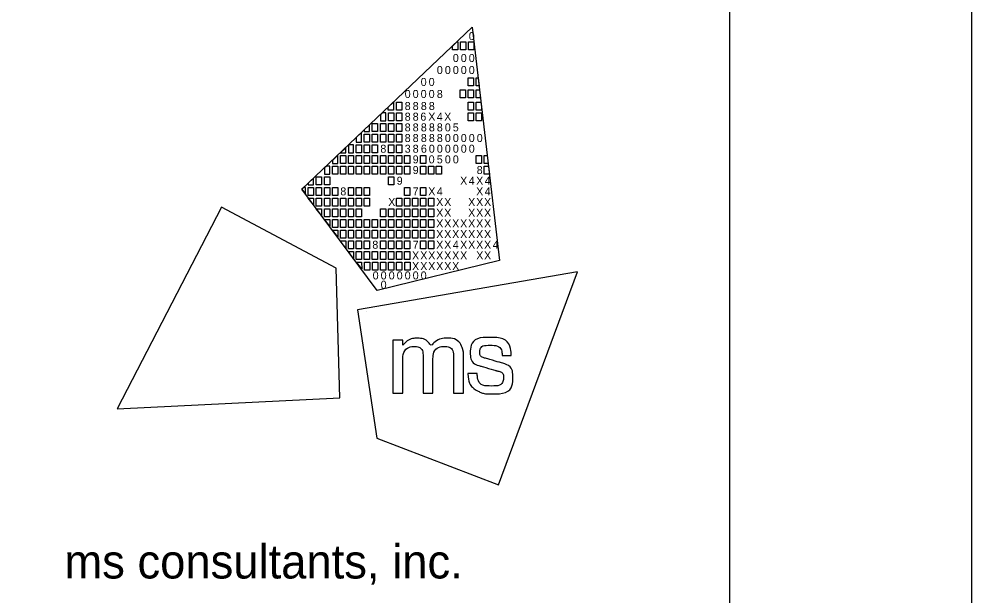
# Model space of a CAD drawing. Extents: x 0 to 34, y 0 to 22.
# Drawn here: x 32.034 to 34, y 3.413 to 4.603 of the extents above; entities that cross this region are included whole.
import ezdxf

# ---------------------------------------------------------------- set-up
doc = ezdxf.new("R2010")
doc.units = 0
for name, color, linetype in [('SH_Border', 7, 'Continuous'), ('SH_Cut_Line', 7, 'Continuous'), ('SH_Data', 7, 'Continuous')]:
    doc.layers.add(name, color=color, linetype=linetype)

msp = doc.modelspace()

# ---------------------------------------------------------------- linework, layer by layer
at = {"layer": 'SH_Border'}
for p, q in [((32.6175, 4.2519), (32.9688, 4.5861)), ((32.9688, 4.5861), (32.9688, 4.5861)), ((32.9688, 4.5861), (33.0253, 4.1052)), ((32.773, 4.043), (32.6175, 4.2519)), ((33.0253, 4.1052), (32.773, 4.043))]:
    msp.add_line(p, q, dxfattribs=at)
for points in [[(1.5, 21.5), (33.5, 21.5), (33.5, 0.5), (1.5, 0.5)], [(32.9279, 4.5472), (32.9369, 4.5558), (32.9389, 4.5558), (32.9389, 4.5393), (32.9279, 4.5393)], [(32.9444, 4.5558), (32.9554, 4.5558), (32.9554, 4.5393), (32.9444, 4.5393)], [(32.9609, 4.5558), (32.9719, 4.5558), (32.9719, 4.5393), (32.9609, 4.5393)], [(32.9606, 4.4815), (32.9716, 4.4815), (32.9716, 4.465), (32.9606, 4.465)], [(32.9771, 4.4815), (32.9811, 4.4815), (32.983, 4.465), (32.9771, 4.465)], [(32.9441, 4.4567), (32.9551, 4.4567), (32.9551, 4.4402), (32.9441, 4.4402)], [(32.9606, 4.4567), (32.9716, 4.4567), (32.9716, 4.4402), (32.9606, 4.4402)], [(32.9771, 4.4567), (32.984, 4.4567), (32.9859, 4.4402), (32.9771, 4.4402)], [(32.7953, 4.4211), (32.8064, 4.4316), (32.8064, 4.4154), (32.7953, 4.4154)], [(32.8123, 4.4319), (32.8233, 4.4319), (32.8233, 4.4154), (32.8123, 4.4154)], [(32.9606, 4.4319), (32.9716, 4.4319), (32.9716, 4.4154), (32.9606, 4.4154)], [(32.9771, 4.4319), (32.9869, 4.4319), (32.9881, 4.4218), (32.9881, 4.4154), (32.9771, 4.4154)], [(32.7958, 4.4099), (32.8068, 4.4099), (32.8068, 4.3934), (32.7958, 4.3934)], [(32.8123, 4.4099), (32.8233, 4.4099), (32.8233, 4.3934), (32.8123, 4.3934)], [(32.9606, 4.4099), (32.9716, 4.4099), (32.9716, 4.3934), (32.9606, 4.3934)], [(32.9771, 4.4099), (32.9881, 4.4099), (32.9881, 4.3934), (32.9771, 4.3934)], [(32.7627, 4.3879), (32.7737, 4.3879), (32.7737, 4.3714), (32.7627, 4.3714)], [(32.7793, 4.3879), (32.7903, 4.3879), (32.7903, 4.3714), (32.7793, 4.3714)], [(32.7958, 4.3879), (32.8068, 4.3879), (32.8068, 4.3714), (32.7958, 4.3714)], [(32.8123, 4.3879), (32.8233, 4.3879), (32.8233, 4.3714), (32.8123, 4.3714)], [(32.7462, 4.3659), (32.7572, 4.3659), (32.7572, 4.3494), (32.7462, 4.3494)], [(32.7627, 4.3659), (32.7737, 4.3659), (32.7737, 4.3494), (32.7627, 4.3494)], [(32.7793, 4.3659), (32.7903, 4.3659), (32.7903, 4.3494), (32.7793, 4.3494)], [(32.7958, 4.3659), (32.8068, 4.3659), (32.8068, 4.3494), (32.7958, 4.3494)], [(32.8123, 4.3659), (32.8233, 4.3659), (32.8233, 4.3494), (32.8123, 4.3494)], [(32.7297, 4.3439), (32.7407, 4.3439), (32.7407, 4.3273), (32.7297, 4.3273)], [(32.7462, 4.3439), (32.7572, 4.3439), (32.7572, 4.3273), (32.7462, 4.3273)], [(32.7627, 4.3439), (32.7737, 4.3439), (32.7737, 4.3273), (32.7627, 4.3273)], [(32.7958, 4.3439), (32.8068, 4.3439), (32.8068, 4.3273), (32.7958, 4.3273)], [(32.8123, 4.3439), (32.8233, 4.3439), (32.8233, 4.3273), (32.8123, 4.3273)], [(32.6967, 4.3218), (32.7077, 4.3218), (32.7077, 4.3053), (32.6967, 4.3053)], [(32.7132, 4.3218), (32.7242, 4.3218), (32.7242, 4.3053), (32.7132, 4.3053)], [(32.7297, 4.3218), (32.7407, 4.3218), (32.7407, 4.3053), (32.7297, 4.3053)], [(32.7462, 4.3218), (32.7572, 4.3218), (32.7572, 4.3053), (32.7462, 4.3053)], [(32.7627, 4.3218), (32.7737, 4.3218), (32.7737, 4.3053), (32.7627, 4.3053)], [(32.7793, 4.3218), (32.7903, 4.3218), (32.7903, 4.3053), (32.7793, 4.3053)], [(32.7958, 4.3218), (32.8068, 4.3218), (32.8068, 4.3053), (32.7958, 4.3053)], [(32.8123, 4.3218), (32.8233, 4.3218), (32.8233, 4.3053), (32.8123, 4.3053)], [(32.8288, 4.3218), (32.8398, 4.3218), (32.8398, 4.3053), (32.8288, 4.3053)], [(32.8618, 4.3218), (32.8728, 4.3218), (32.8728, 4.3053), (32.8618, 4.3053)], [(32.9771, 4.3218), (32.9881, 4.3218), (32.9881, 4.3053), (32.9771, 4.3053)], [(32.9935, 4.3218), (32.9998, 4.3218), (33.0018, 4.3053), (32.9935, 4.3053)], [(32.6802, 4.2998), (32.6912, 4.2998), (32.6912, 4.2833), (32.6802, 4.2833)], [(32.6967, 4.2998), (32.7077, 4.2998), (32.7077, 4.2833), (32.6967, 4.2833)], [(32.7132, 4.2998), (32.7242, 4.2998), (32.7242, 4.2833), (32.7132, 4.2833)], [(32.7297, 4.2998), (32.7407, 4.2998), (32.7407, 4.2833), (32.7297, 4.2833)], [(32.7462, 4.2998), (32.7572, 4.2998), (32.7572, 4.2833), (32.7462, 4.2833)], [(32.7627, 4.2998), (32.7737, 4.2998), (32.7737, 4.2833), (32.7627, 4.2833)], [(32.7793, 4.2998), (32.7903, 4.2998), (32.7903, 4.2833), (32.7793, 4.2833)], [(32.7958, 4.2998), (32.8068, 4.2998), (32.8068, 4.2833), (32.7958, 4.2833)], [(32.8123, 4.2998), (32.8233, 4.2998), (32.8233, 4.2833), (32.8123, 4.2833)], [(32.8288, 4.2998), (32.8398, 4.2998), (32.8398, 4.2833), (32.8288, 4.2833)], [(32.8618, 4.2998), (32.8728, 4.2998), (32.8728, 4.2833), (32.8618, 4.2833)], [(32.8783, 4.2998), (32.8893, 4.2998), (32.8893, 4.2833), (32.8783, 4.2833)], [(32.8947, 4.2998), (32.9057, 4.2998), (32.9057, 4.2833), (32.8947, 4.2833)], [(32.9935, 4.2998), (33.0024, 4.2998), (33.0044, 4.2833), (32.9935, 4.2833)], [(32.6471, 4.2778), (32.6581, 4.2778), (32.6581, 4.2613), (32.6471, 4.2613)], [(32.6637, 4.2778), (32.6747, 4.2778), (32.6747, 4.2613), (32.6637, 4.2613)], [(32.7958, 4.2778), (32.8068, 4.2778), (32.8068, 4.2613), (32.7958, 4.2613)], [(32.6306, 4.2558), (32.6416, 4.2558), (32.6416, 4.2393), (32.6306, 4.2393)], [(32.6471, 4.2558), (32.6581, 4.2558), (32.6581, 4.2393), (32.6471, 4.2393)], [(32.6637, 4.2558), (32.6747, 4.2558), (32.6747, 4.2393), (32.6637, 4.2393)], [(32.6802, 4.2558), (32.6912, 4.2558), (32.6912, 4.2393), (32.6802, 4.2393)], [(32.7132, 4.2558), (32.7242, 4.2558), (32.7242, 4.2393), (32.7132, 4.2393)], [(32.7297, 4.2558), (32.7407, 4.2558), (32.7407, 4.2393), (32.7297, 4.2393)], [(32.7462, 4.2558), (32.7572, 4.2558), (32.7572, 4.2393), (32.7462, 4.2393)], [(32.8288, 4.2558), (32.8398, 4.2558), (32.8398, 4.2393), (32.8288, 4.2393)], [(32.8618, 4.2558), (32.8728, 4.2558), (32.8728, 4.2393), (32.8618, 4.2393)], [(32.6306, 4.2338), (32.6416, 4.2338), (32.6416, 4.22)], [(32.6471, 4.2338), (32.6581, 4.2338), (32.6581, 4.2173), (32.6471, 4.2173)], [(32.6637, 4.2338), (32.6747, 4.2338), (32.6747, 4.2173), (32.6637, 4.2173)], [(32.6802, 4.2338), (32.6912, 4.2338), (32.6912, 4.2173), (32.6802, 4.2173)], [(32.6967, 4.2338), (32.7077, 4.2338), (32.7077, 4.2173), (32.6967, 4.2173)], [(32.7132, 4.2338), (32.7242, 4.2338), (32.7242, 4.2173), (32.7132, 4.2173)], [(32.7297, 4.2338), (32.7407, 4.2338), (32.7407, 4.2173), (32.7297, 4.2173)], [(32.7462, 4.2338), (32.7572, 4.2338), (32.7572, 4.2173), (32.7462, 4.2173)], [(32.8123, 4.2338), (32.8233, 4.2338), (32.8233, 4.2173), (32.8123, 4.2173)], [(32.8288, 4.2338), (32.8398, 4.2338), (32.8398, 4.2173), (32.8288, 4.2173)], [(32.8453, 4.2338), (32.8563, 4.2338), (32.8563, 4.2173), (32.8453, 4.2173)], [(32.8618, 4.2338), (32.8728, 4.2338), (32.8728, 4.2173), (32.8618, 4.2173)], [(32.8783, 4.2338), (32.8893, 4.2338), (32.8893, 4.2173), (32.8783, 4.2173)], [(32.6471, 4.2117), (32.6581, 4.2117), (32.6581, 4.198)], [(32.6637, 4.2117), (32.6747, 4.2117), (32.6747, 4.1952), (32.6637, 4.1952)], [(32.6802, 4.2117), (32.6912, 4.2117), (32.6912, 4.1952), (32.6802, 4.1952)], [(32.6967, 4.2117), (32.7077, 4.2117), (32.7077, 4.1952), (32.6967, 4.1952)], [(32.7132, 4.2117), (32.7242, 4.2117), (32.7242, 4.1952), (32.7132, 4.1952)], [(32.7297, 4.2117), (32.7407, 4.2117), (32.7407, 4.1952), (32.7297, 4.1952)], [(32.7793, 4.2117), (32.7903, 4.2117), (32.7903, 4.1952), (32.7793, 4.1952)], [(32.7958, 4.2117), (32.8068, 4.2117), (32.8068, 4.1952), (32.7958, 4.1952)], [(32.8123, 4.2117), (32.8233, 4.2117), (32.8233, 4.1952), (32.8123, 4.1952)], [(32.8288, 4.2117), (32.8398, 4.2117), (32.8398, 4.1952), (32.8288, 4.1952)], [(32.8453, 4.2117), (32.8563, 4.2117), (32.8563, 4.1952), (32.8453, 4.1952)], [(32.8618, 4.2117), (32.8728, 4.2117), (32.8728, 4.1952), (32.8618, 4.1952)], [(32.8783, 4.2117), (32.8893, 4.2117), (32.8893, 4.1952), (32.8783, 4.1952)], [(32.6637, 4.1897), (32.6747, 4.1897), (32.6747, 4.176)], [(32.6747, 4.1897), (32.6747, 4.1897), (32.6747, 4.1897)], [(32.6802, 4.1897), (32.6912, 4.1897), (32.6912, 4.1732), (32.6802, 4.1732)], [(32.6967, 4.1897), (32.7077, 4.1897), (32.7077, 4.1732), (32.6967, 4.1732)], [(32.7132, 4.1897), (32.7242, 4.1897), (32.7242, 4.1732), (32.7132, 4.1732)], [(32.7297, 4.1897), (32.7407, 4.1897), (32.7407, 4.1732), (32.7297, 4.1732)], [(32.7462, 4.1897), (32.7572, 4.1897), (32.7572, 4.1732), (32.7462, 4.1732)], [(32.7627, 4.1897), (32.7737, 4.1897), (32.7737, 4.1732), (32.7627, 4.1732)], [(32.7793, 4.1897), (32.7903, 4.1897), (32.7903, 4.1732), (32.7793, 4.1732)], [(32.7958, 4.1897), (32.8068, 4.1897), (32.8068, 4.1732), (32.7958, 4.1732)], [(32.8123, 4.1897), (32.8233, 4.1897), (32.8233, 4.1732), (32.8123, 4.1732)], [(32.8288, 4.1897), (32.8398, 4.1897), (32.8398, 4.1732), (32.8288, 4.1732)], [(32.8453, 4.1897), (32.8563, 4.1897), (32.8563, 4.1732), (32.8453, 4.1732)], [(32.8618, 4.1897), (32.8728, 4.1897), (32.8728, 4.1732), (32.8618, 4.1732)], [(32.8783, 4.1897), (32.8893, 4.1897), (32.8893, 4.1732), (32.8783, 4.1732)], [(32.6802, 4.1677), (32.6912, 4.1677), (32.6912, 4.154)], [(32.6967, 4.1677), (32.7077, 4.1677), (32.7077, 4.1512), (32.6967, 4.1512)], [(32.7132, 4.1677), (32.7242, 4.1677), (32.7242, 4.1512), (32.7132, 4.1512)], [(32.7297, 4.1677), (32.7407, 4.1677), (32.7407, 4.1512), (32.7297, 4.1512)], [(32.7462, 4.1677), (32.7572, 4.1677), (32.7572, 4.1512), (32.7462, 4.1512)], [(32.7627, 4.1677), (32.7737, 4.1677), (32.7737, 4.1512), (32.7627, 4.1512)], [(32.7793, 4.1677), (32.7903, 4.1677), (32.7903, 4.1512), (32.7793, 4.1512)], [(32.7958, 4.1677), (32.8068, 4.1677), (32.8068, 4.1512), (32.7958, 4.1512)], [(32.8123, 4.1677), (32.8233, 4.1677), (32.8233, 4.1512), (32.8123, 4.1512)], [(32.8288, 4.1677), (32.8398, 4.1677), (32.8398, 4.1512), (32.8288, 4.1512)], [(32.8453, 4.1677), (32.8563, 4.1677), (32.8563, 4.1512), (32.8453, 4.1512)], [(32.8618, 4.1677), (32.8728, 4.1677), (32.8728, 4.1512), (32.8618, 4.1512)], [(32.8783, 4.1677), (32.8893, 4.1677), (32.8893, 4.1512), (32.8783, 4.1512)], [(32.7077, 4.1305), (32.6965, 4.1457), (32.7077, 4.1457)], [(32.7132, 4.1457), (32.7242, 4.1457), (32.7242, 4.1292), (32.7132, 4.1292)], [(32.7297, 4.1457), (32.7407, 4.1457), (32.7407, 4.1292), (32.7297, 4.1292)], [(32.7462, 4.1457), (32.7572, 4.1457), (32.7572, 4.1292), (32.7462, 4.1292)], [(32.7793, 4.1457), (32.7903, 4.1457), (32.7903, 4.1292), (32.7793, 4.1292)], [(32.7958, 4.1457), (32.8068, 4.1457), (32.8068, 4.1292), (32.7958, 4.1292)], [(32.8123, 4.1457), (32.8233, 4.1457), (32.8233, 4.1292), (32.8123, 4.1292)], [(32.8288, 4.1457), (32.8398, 4.1457), (32.8398, 4.1292), (32.8288, 4.1292)], [(32.8618, 4.1457), (32.8728, 4.1457), (32.8728, 4.1292), (32.8618, 4.1292)], [(32.8783, 4.1457), (32.8893, 4.1457), (32.8893, 4.1292), (32.8783, 4.1292)], [(32.724, 4.1082), (32.7132, 4.1237), (32.7242, 4.1237)], [(32.7297, 4.1237), (32.7407, 4.1237), (32.7407, 4.1072), (32.7297, 4.1072)], [(32.7462, 4.1237), (32.7572, 4.1237), (32.7572, 4.1072), (32.7462, 4.1072)], [(32.7627, 4.1237), (32.7737, 4.1237), (32.7737, 4.1072), (32.7627, 4.1072)], [(32.7793, 4.1237), (32.7903, 4.1237), (32.7903, 4.1072), (32.7793, 4.1072)], [(32.7958, 4.1237), (32.8068, 4.1237), (32.8068, 4.1072), (32.7958, 4.1072)], [(32.8123, 4.1237), (32.8233, 4.1237), (32.8233, 4.1072), (32.8123, 4.1072)], [(32.8288, 4.1237), (32.8398, 4.1237), (32.8398, 4.1072), (32.8288, 4.1072)], [(32.7302, 4.1017), (32.7407, 4.1017), (32.7408, 4.0875)], [(32.7463, 4.1017), (32.7573, 4.1017), (32.7573, 4.0852), (32.7463, 4.0852)], [(32.763, 4.1017), (32.774, 4.1017), (32.774, 4.0852), (32.763, 4.0852)], [(32.7794, 4.1017), (32.7904, 4.1017), (32.7904, 4.0852), (32.7794, 4.0852)], [(32.796, 4.1017), (32.807, 4.1017), (32.807, 4.0852), (32.796, 4.0852)], [(32.8129, 4.1017), (32.8239, 4.1017), (32.8239, 4.0851), (32.8129, 4.0851)], [(32.8296, 4.1017), (32.8406, 4.1017), (32.8406, 4.0851), (32.8296, 4.0851)]]:
    msp.add_lwpolyline(points, close=True, dxfattribs=at)
for points in [[(32.7903, 4.4099), (32.7836, 4.4099), (32.7793, 4.4058), (32.7793, 4.3934), (32.7903, 4.3934), (32.7903, 4.4099)], [(32.7572, 4.3849), (32.7462, 4.3744), (32.7462, 4.3714), (32.7572, 4.3714), (32.7572, 4.3849)], [(32.7407, 4.3691), (32.7297, 4.3587), (32.7297, 4.3494), (32.7407, 4.3494), (32.7407, 4.3691)], [(32.7077, 4.3377), (32.6968, 4.3273), (32.7077, 4.3273), (32.7077, 4.3377)], [(32.7242, 4.3439), (32.7141, 4.3439), (32.7132, 4.343), (32.7132, 4.3273), (32.7242, 4.3273), (32.7242, 4.3439)], [(32.6912, 4.322), (32.6802, 4.3115), (32.6802, 4.3053), (32.6912, 4.3053), (32.6912, 4.322)], [(32.6747, 4.2998), (32.6679, 4.2998), (32.6637, 4.2958), (32.6637, 4.2833), (32.6747, 4.2833), (32.6747, 4.2998)], [(32.6416, 4.2749), (32.6306, 4.2644), (32.6306, 4.2613), (32.6416, 4.2613), (32.6416, 4.2749)], [(32.6251, 4.2558), (32.6216, 4.2558), (32.6175, 4.2519), (32.6251, 4.2417), (32.6251, 4.2558)], [(32.4512, 4.2149), (32.2359, 3.7988), (32.6956, 3.8215), (32.6884, 4.0892), (32.4512, 4.2149)], [(33.0229, 3.6422), (33.1859, 4.0814), (32.7324, 4.0029), (32.7722, 3.7381), (33.0229, 3.6422)]]:
    msp.add_lwpolyline(points, dxfattribs=at)
for points in [[(32.8048, 3.8315), (32.8048, 3.8315), (32.8048, 3.9409), (32.8048, 3.9409), (32.8048, 3.9409), (32.8255, 3.9409), (32.8255, 3.9409), (32.8255, 3.9409), (32.8255, 3.9297), (32.8255, 3.9297), (32.8346, 3.9399), (32.8457, 3.9445), (32.8555, 3.9445), (32.8688, 3.9445), (32.8791, 3.9372), (32.8837, 3.9266), (32.8915, 3.9381), (32.905, 3.9446), (32.9166, 3.9446), (32.9325, 3.9446), (32.9451, 3.935), (32.9494, 3.9213), (32.9494, 3.9212), (32.9494, 3.9212), (32.9494, 3.9212), (32.9501, 3.919), (32.9506, 3.9172), (32.9506, 3.9071), (32.9506, 3.9071), (32.9506, 3.8314), (32.9506, 3.8314), (32.9506, 3.8314), (32.9303, 3.8314), (32.9303, 3.8314), (32.9303, 3.8314), (32.9303, 3.9048), (32.9303, 3.9048), (32.9303, 3.9201), (32.9219, 3.9274), (32.911, 3.9274), (32.8995, 3.9274), (32.8879, 3.9171), (32.8879, 3.9001), (32.8879, 3.9001), (32.8879, 3.8315), (32.8879, 3.8315), (32.8879, 3.8315), (32.8674, 3.8315), (32.8674, 3.8315), (32.8674, 3.8315), (32.8674, 3.9059), (32.8674, 3.9059), (32.8674, 3.9203), (32.8588, 3.9274), (32.8496, 3.9274), (32.8384, 3.9274), (32.8254, 3.917), (32.8254, 3.8962), (32.8254, 3.8962), (32.8254, 3.8315), (32.8254, 3.8315), (32.8254, 3.8315), (32.8048, 3.8315), (32.8048, 3.8315)], [(32.9595, 3.8709), (32.9595, 3.8709), (32.9595, 3.8717), (32.9595, 3.8717), (32.9595, 3.8717), (32.9603, 3.8717), (32.9603, 3.8717), (32.9603, 3.8717), (32.9783, 3.8717), (32.9783, 3.8717), (32.9783, 3.8717), (32.9789, 3.8717), (32.9789, 3.8717), (32.9789, 3.8717), (32.979, 3.871), (32.979, 3.871), (32.9803, 3.8554), (32.9887, 3.846), (33.009, 3.846), (33.0273, 3.846), (33.0333, 3.8554), (33.0333, 3.8631), (33.0333, 3.8732), (33.0256, 3.8758), (33.0175, 3.878), (33.0175, 3.878), (32.987, 3.8867), (32.987, 3.8867), (32.972, 3.8909), (32.9648, 3.9019), (32.9648, 3.9142), (32.9648, 3.9303), (32.9768, 3.9462), (33.0052, 3.9462), (33.0348, 3.9462), (33.0489, 3.9285), (33.0489, 3.9095), (33.0489, 3.9095), (33.0489, 3.9087), (33.0489, 3.9087), (33.0489, 3.9087), (33.0482, 3.9087), (33.0482, 3.9087), (33.0482, 3.9087), (33.0312, 3.9087), (33.0312, 3.9087), (33.0312, 3.9087), (33.0305, 3.9087), (33.0305, 3.9087), (33.0305, 3.9087), (33.0305, 3.9094), (33.0305, 3.9094), (33.0301, 3.9208), (33.0226, 3.93), (33.0056, 3.93), (32.9891, 3.93), (32.9843, 3.9218), (32.9843, 3.9157), (32.9843, 3.9108), (32.9869, 3.9059), (32.9959, 3.9033), (32.9959, 3.9033), (33.0255, 3.8948), (33.0255, 3.8948), (33.0462, 3.8889), (33.0527, 3.8777), (33.0527, 3.8639), (33.0527, 3.8462), (33.041, 3.8298), (33.0087, 3.8298), (32.9952, 3.8298), (32.9877, 3.8321), (32.9823, 3.8348), (32.969, 3.8414), (32.9609, 3.8536), (32.9595, 3.8709)]]:
    msp.add_open_spline(points, degree=3, dxfattribs=at)
at = {"layer": 'SH_Cut_Line'}
msp.add_lwpolyline([(0, 0), (34, 0), (34, 22), (0, 22)], close=True, dxfattribs=at)
at = {"layer": 'SH_Data'}
msp.add_line((32.75, 4), (32.75, 4), dxfattribs=at)

# ---------------------------------------------------------------- texts
at = {"layer": 'SH_Border'}
for s, height, p in [('0', 0.0165, (32.9617, 4.5597)), ('0', 0.0165, (32.9288, 4.5145)), ('0', 0.0165, (32.9452, 4.5145)), ('0', 0.0165, (32.9617, 4.5145)), ('0', 0.0165, (32.8958, 4.4897)), ('0', 0.0165, (32.9123, 4.4897)), ('0', 0.0165, (32.9288, 4.4897)), ('0', 0.0165, (32.9452, 4.4897)), ('0', 0.0165, (32.9617, 4.4897)), ('0', 0.0165, (32.8625, 4.465)), ('0', 0.0165, (32.879, 4.465)), ('0', 0.0165, (32.8295, 4.4402)), ('0', 0.0165, (32.846, 4.4402)), ('0', 0.0165, (32.8625, 4.4402)), ('0', 0.0165, (32.879, 4.4402)), ('8', 0.0165, (32.8958, 4.4402)), ('8', 0.0165, (32.8295, 4.4154)), ('8', 0.0165, (32.846, 4.4154)), ('8', 0.0165, (32.8628, 4.4154)), ('8', 0.0165, (32.8793, 4.4154)), ('8', 0.0165, (32.8295, 4.3934)), ('8', 0.0165, (32.846, 4.3934)), ('6', 0.0165, (32.8618, 4.3934)), ('X', 0.0165, (32.8781, 4.3934)), ('4', 0.0165, (32.8958, 4.3934)), ('X', 0.0165, (32.911, 4.3934)), ('8', 0.0165, (32.8295, 4.3713)), ('8', 0.0165, (32.846, 4.3713)), ('8', 0.0165, (32.8628, 4.3713)), ('8', 0.0165, (32.8794, 4.3713)), ('8', 0.0165, (32.8958, 4.3713)), ('0', 0.0165, (32.9123, 4.3713)), ('5', 0.0165, (32.9287, 4.3713)), ('8', 0.0165, (32.8295, 4.3494)), ('8', 0.0165, (32.846, 4.3494)), ('8', 0.0165, (32.8628, 4.3494)), ('8', 0.0165, (32.8794, 4.3494)), ('8', 0.0165, (32.8958, 4.3494)), ('0', 0.0165, (32.9123, 4.3494)), ('0', 0.0165, (32.9288, 4.3494)), ('0', 0.0165, (32.9452, 4.3494)), ('0', 0.0165, (32.9617, 4.3494)), ('0', 0.0165, (32.9782, 4.3494)), ('8', 0.0165, (32.7793, 4.3273)), ('3', 0.0165, (32.8295, 4.3273)), ('8', 0.0165, (32.846, 4.3273)), ('6', 0.0165, (32.8629, 4.3273)), ('0', 0.0165, (32.8793, 4.3273)), ('0', 0.0165, (32.8958, 4.3273)), ('0', 0.0165, (32.9123, 4.3273)), ('0', 0.0165, (32.9288, 4.3273)), ('0', 0.0165, (32.9452, 4.3273)), ('0', 0.0165, (32.9617, 4.3273)), ('9', 0.0165, (32.846, 4.3053)), ('0', 0.0165, (32.879, 4.3053)), ('5', 0.0165, (32.8957, 4.3053)), ('0', 0.0165, (32.9123, 4.3053)), ('0', 0.0165, (32.9288, 4.3053)), ('9', 0.0165, (32.846, 4.2833)), ('8', 0.0165, (32.9781, 4.2833)), ('9', 0.0165, (32.813, 4.2613)), ('X', 0.0165, (32.9439, 4.2613)), ('4', 0.0165, (32.9617, 4.2613)), ('X', 0.0165, (32.9769, 4.2613)), ('4', 0.0165, (32.9946, 4.2613)), ('8', 0.0165, (32.6967, 4.2393)), ('7', 0.0165, (32.846, 4.2393)), ('X', 0.0165, (32.8781, 4.2393)), ('4', 0.0165, (32.8958, 4.2393)), ('X', 0.0165, (32.9769, 4.2393)), ('4', 0.0165, (32.9946, 4.2393)), ('X', 0.0165, (32.7955, 4.2173)), ('X', 0.0165, (32.8945, 4.2173)), ('X', 0.0165, (32.911, 4.2173)), ('X', 0.0165, (32.9604, 4.2173)), ('X', 0.0165, (32.9769, 4.2173)), ('X', 0.0165, (32.9933, 4.2173)), ('X', 0.0165, (32.8945, 4.1952)), ('X', 0.0165, (32.911, 4.1952)), ('X', 0.0165, (32.9604, 4.1952)), ('X', 0.0165, (32.9769, 4.1952)), ('X', 0.0165, (32.9933, 4.1952)), ('X', 0.0165, (32.8945, 4.1732)), ('X', 0.0165, (32.911, 4.1732)), ('X', 0.0165, (32.9274, 4.1732)), ('X', 0.0165, (32.9439, 4.1732)), ('X', 0.0165, (32.9604, 4.1732)), ('X', 0.0165, (32.9769, 4.1732)), ('X', 0.0165, (32.9933, 4.1732)), ('X', 0.0165, (32.8945, 4.1512)), ('X', 0.0165, (32.911, 4.1512)), ('X', 0.0165, (32.9274, 4.1512)), ('X', 0.0165, (32.9439, 4.1512)), ('X', 0.0165, (32.9604, 4.1512)), ('X', 0.0165, (32.9769, 4.1512)), ('X', 0.0165, (32.9933, 4.1512)), ('8', 0.0165, (32.7627, 4.1292)), ('7', 0.0165, (32.846, 4.1292)), ('X', 0.0165, (32.8945, 4.1292)), ('X', 0.0165, (32.911, 4.1292)), ('4', 0.0165, (32.9288, 4.1292)), ('X', 0.0165, (32.9439, 4.1292)), ('X', 0.0165, (32.9604, 4.1292)), ('X', 0.0165, (32.9769, 4.1292)), ('X', 0.0165, (32.9933, 4.1292)), ('4', 0.0165, (33.0111, 4.1292)), ('X', 0.0165, (32.8447, 4.1072)), ('X', 0.0165, (32.8616, 4.1072)), ('X', 0.0165, (32.878, 4.1072)), ('X', 0.0165, (32.8945, 4.1072)), ('X', 0.0165, (32.911, 4.1072)), ('X', 0.0165, (32.9274, 4.1072)), ('X', 0.0165, (32.9439, 4.1072)), ('X', 0.0165, (32.9771, 4.1072)), ('X', 0.0165, (32.9933, 4.1072)), ('X', 0.0165, (32.8447, 4.0851)), ('X', 0.0165, (32.8616, 4.0851)), ('X', 0.0165, (32.878, 4.0851)), ('X', 0.0165, (32.8945, 4.0851)), ('X', 0.0165, (32.911, 4.0851)), ('X', 0.0165, (32.9274, 4.0851)), ('0', 0.0165, (32.7634, 4.0659)), ('0', 0.0165, (32.7799, 4.0659)), ('0', 0.0165, (32.7965, 4.0659)), ('0', 0.0165, (32.813, 4.0659)), ('0', 0.0165, (32.8295, 4.0659)), ('0', 0.0165, (32.846, 4.0659)), ('0', 0.0165, (32.8625, 4.0659)), ('0', 0.0165, (32.7799, 4.0467)), ('ms consultants, inc.', 0.07, (32.1273, 3.4489))]:
    msp.add_text(s, height=height, rotation=360, dxfattribs=at).set_placement(p)

doc.saveas('drawing.dxf')
